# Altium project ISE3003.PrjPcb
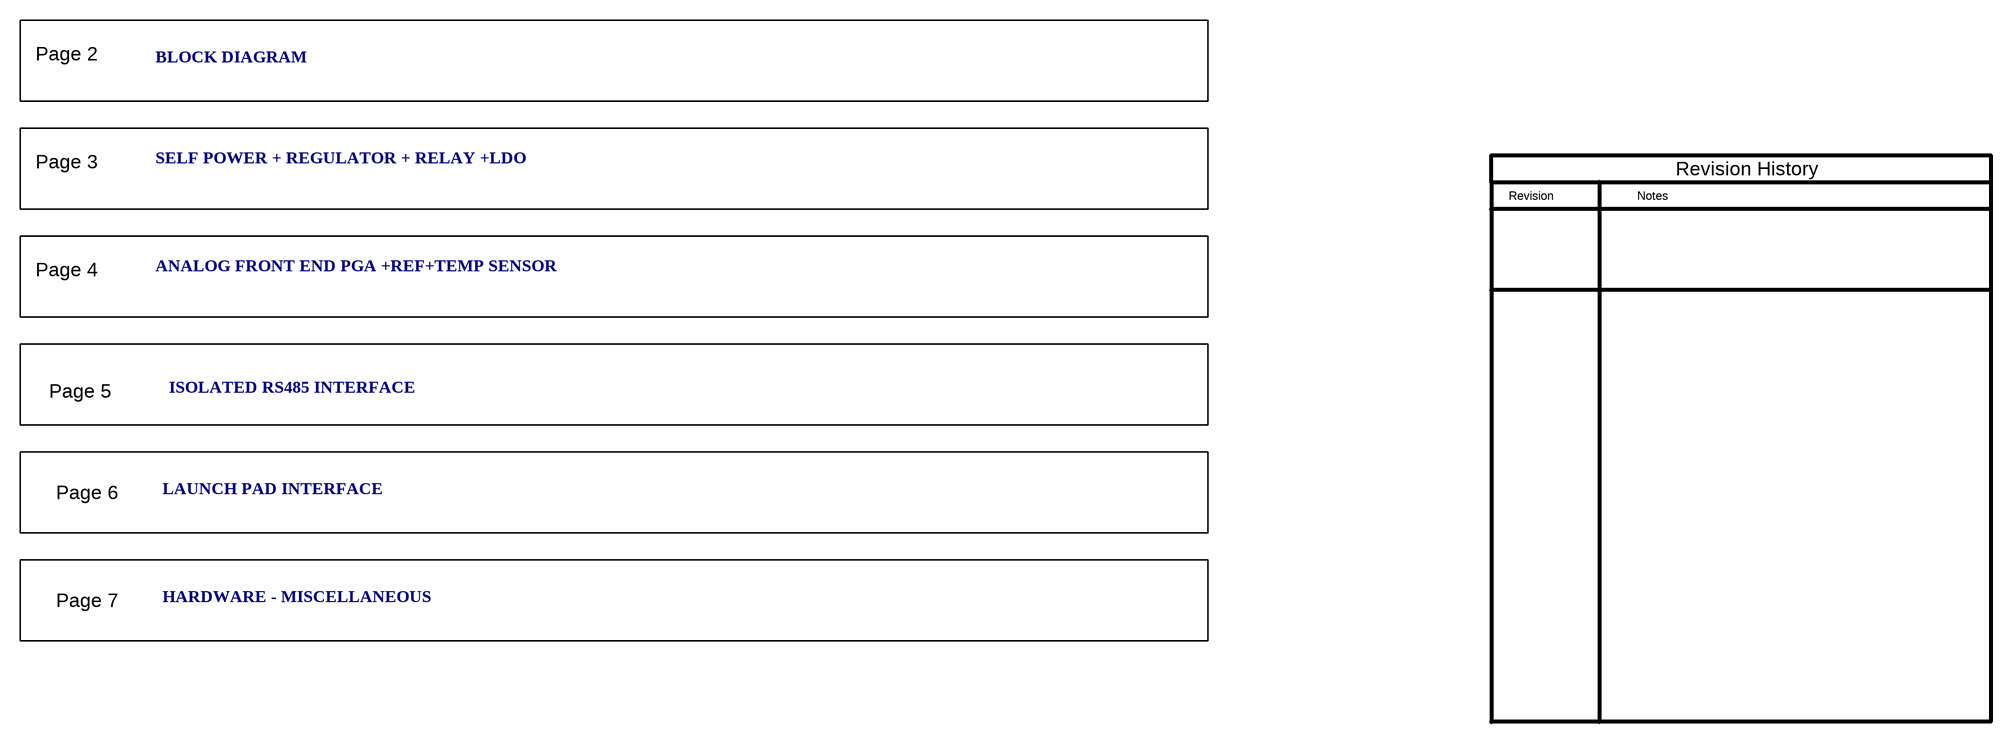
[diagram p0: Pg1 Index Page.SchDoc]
CopyrightYear: 2014; PCB_Layout: Who did the Layout?; PCB_Rev: E1; PRJ_Customer: Public Release; PRJ_Engineer: Enter name of project lead; PRJ_Number: TIDA-00191; PRJ_Title: AFE for Motor Electronic Overload Relays; SCH_Rev: E1; TechSupport: http://www.ti.com/support
7 sheets, 231 parts. Net scope: flat (ports and power ports of the same name join across sheets).
Board file: ISE3003.PcbDoc
Sheets:
  Pg1 Index Page.SchDoc
  Pg2 Block Diagram.SchDoc
  Pg3.SchDoc
  Pg4.SchDoc
  Pg5.SchDoc
  Pg6.SchDoc
  Pg7 Hardware.SchDoc

## Sheet Pg1 Index Page.SchDoc
size 431 x 279 mm; Date: Not shown in title block; ApprovedBy: Not shown in title block; CheckedBy: Not shown in title block; Author: Not shown in title block; CompanyName: Not shown in title block; Engineer: Not shown in title block; Organization: Not shown in title block; Address1: Not shown in title block; Address2: Not shown in title block; Address3: Not shown in title block; Address4: Not shown in title block; DocumentNumber: 1; Revision: Use project parameter SCH_Rev; SheetNumber: 1; SheetTotal: 7; PageSetup: Record=PageOptions|CenterHorizontal=True|CenterVertical=True|PrintScale=1.00|XCorrection=1.00|YCorrection=1.00|PrintKind=0|BorderSize=5000000|LeftOffset=0|BottomOffset=0|Orientation=2|PaperLength=1000|PaperWidth=1000|Scale=100|PaperSource=15|PrintQuality=600|MediaType=1|DitherType=10|PaperKind=Letter|PrintScaleMode=1

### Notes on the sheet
- Page 2
- BLOCK DIAGRAM
- Page 3
- SELF POWER + REGULATOR + RELAY +LDO
- Revision
- Notes
- Revision History
- Page 4
- ANALOG FRONT END PGA +REF+TEMP SENSOR
- Page 5
- ISOLATED RS485 INTERFACE
- Page 6
- LAUNCH PAD INTERFACE
- Page 7
- HARDWARE - MISCELLANEOUS

## Sheet Pg2 Block Diagram.SchDoc
size 431 x 279 mm; Date: Not shown in title block; ApprovedBy: Not shown in title block; CheckedBy: Not shown in title block; Author: Not shown in title block; CompanyName: Not shown in title block; Engineer: Not shown in title block; Organization: Not shown in title block; Address1: Not shown in title block; Address2: Not shown in title block; Address3: Not shown in title block; Address4: Not shown in title block; DocumentNumber: 2; Revision: Use project parameter SCH_Rev; SheetNumber: 2; SheetTotal: 7; PageSetup: Record=PageOptions|CenterHorizontal=True|CenterVertical=True|PrintScale=1.00|XCorrection=1.00|YCorrection=1.00|PrintKind=0|BorderSize=5000000|LeftOffset=0|BottomOffset=0|Orientation=2|PaperLength=1000|PaperWidth=1000|Scale=100|PaperSource=15|PrintQuality=600|MediaType=1|DitherType=10|PaperKind=Letter|PrintScaleMode=1
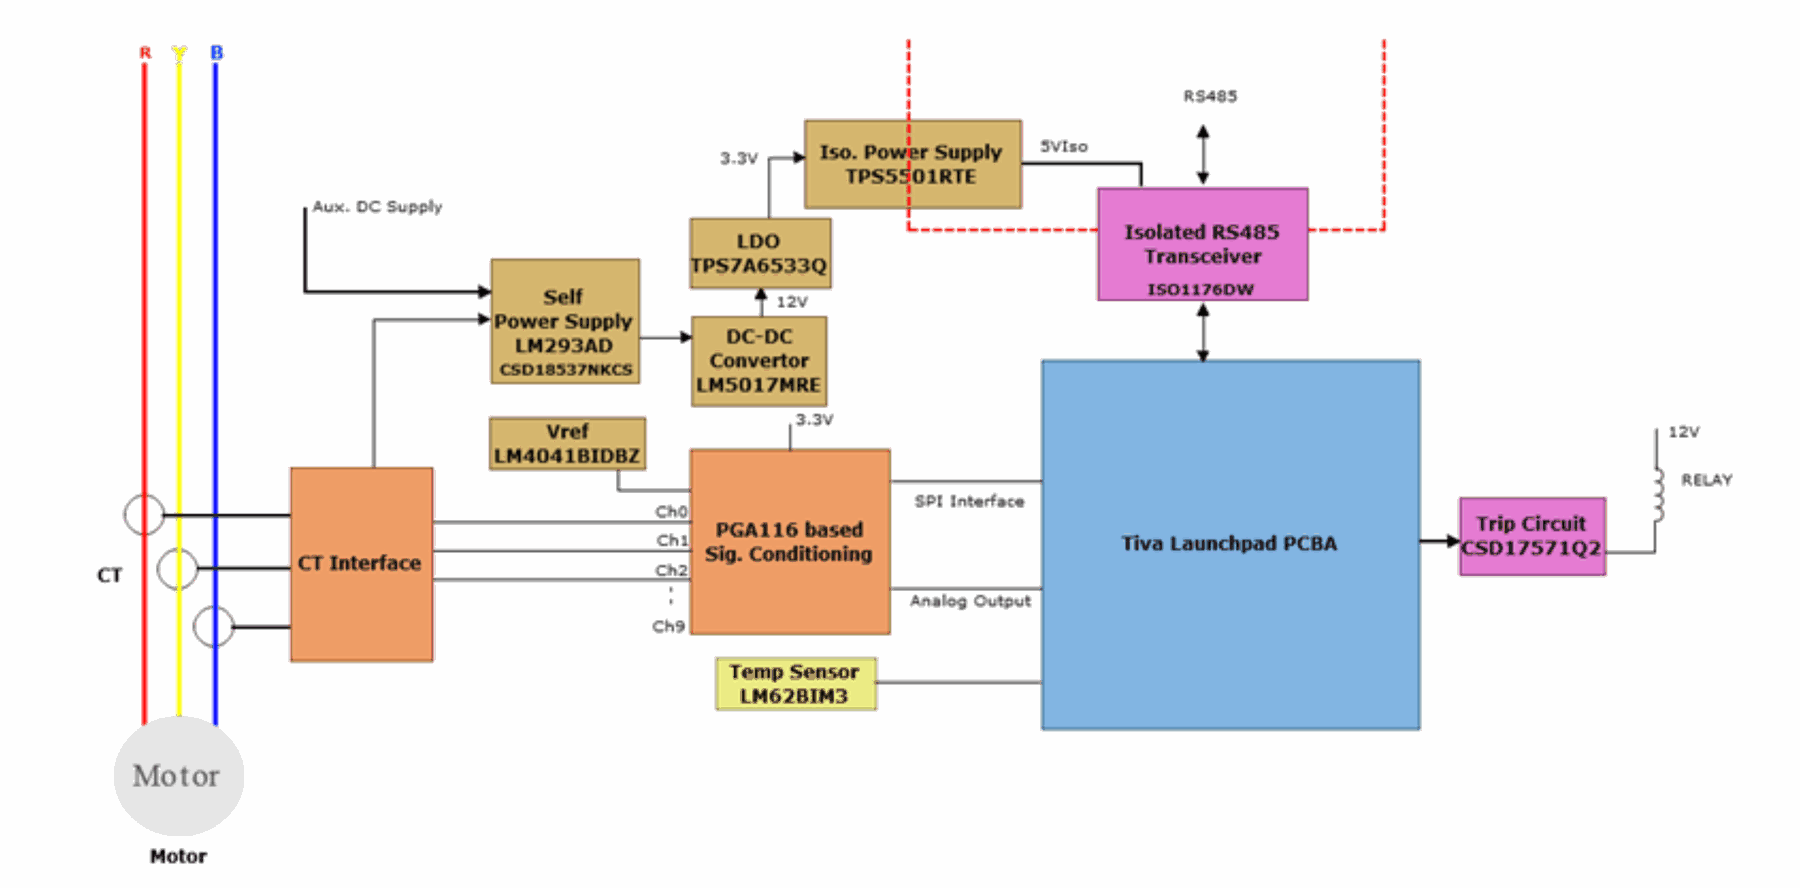
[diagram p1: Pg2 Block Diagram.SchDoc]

## Sheet Pg3.SchDoc
size 431 x 279 mm; Date: Not shown in title block; ApprovedBy: Not shown in title block; CheckedBy: Not shown in title block; Author: Not shown in title block; CompanyName: Not shown in title block; Engineer: Not shown in title block; Organization: Not shown in title block; Address1: Not shown in title block; Address2: Not shown in title block; Address3: Not shown in title block; Address4: Not shown in title block; DocumentNumber: 3; Revision: Use project parameter SCH_Rev; SheetNumber: 3; SheetTotal: 7; PageSetup: Record=PageOptions|CenterHorizontal=True|CenterVertical=True|PrintScale=1.00|XCorrection=1.00|YCorrection=1.00|PrintKind=0|BorderSize=5000000|LeftOffset=0|BottomOffset=0|Orientation=2|PaperLength=1000|PaperWidth=1000|Scale=100|PaperSource=15|PrintQuality=600|MediaType=1|DitherType=10|PaperKind=Letter|PrintScaleMode=1
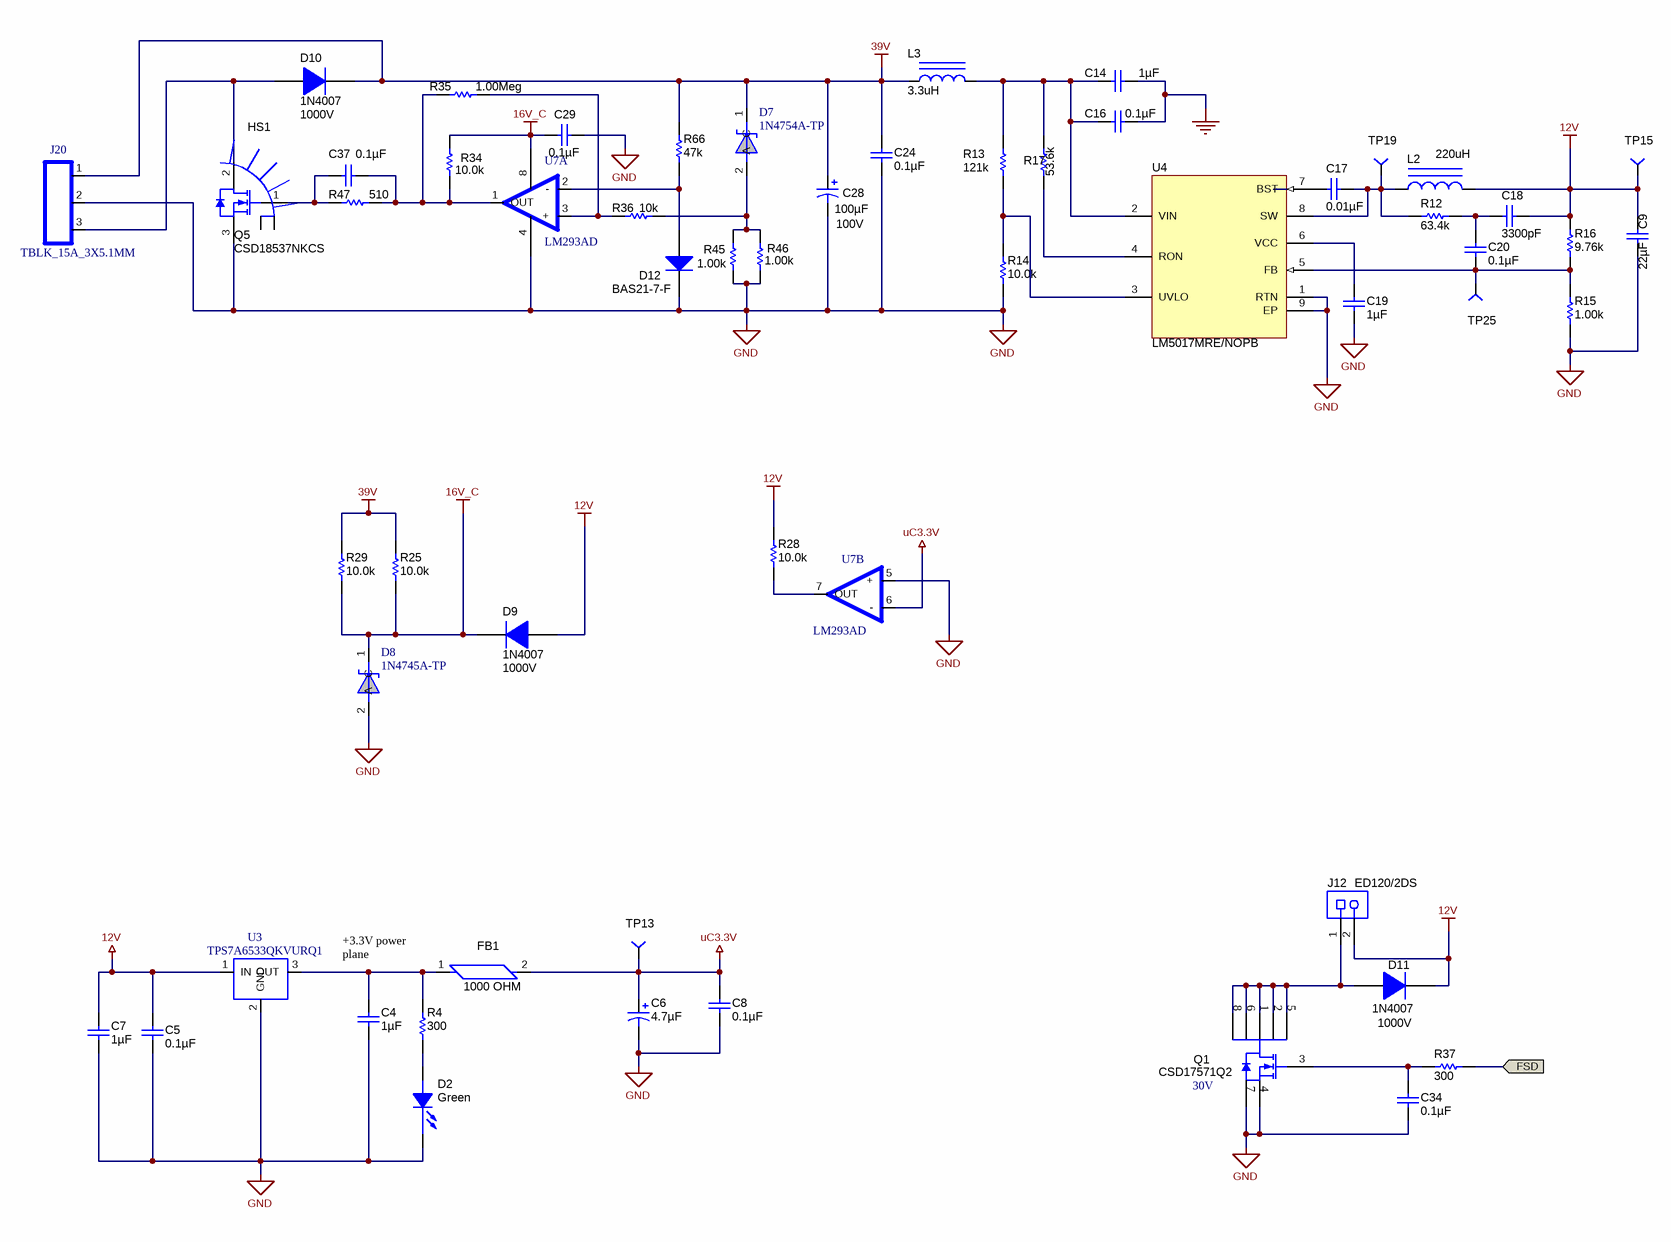
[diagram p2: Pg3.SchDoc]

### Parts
C4  ValueDisplayed: 1µF  [0603]  (hidden comment: C1608X7R1C105K)
C5  ValueDisplayed: 0.1µF  [0603]  (hidden comment: C0603C104K5RACTU)
C6  ValueDisplayed: 4.7µF  [6032-28]  (hidden comment: 293D475X9035C2TE3)
C7  ValueDisplayed: 1µF  [0603]  (hidden comment: C1608X7R1C105K)
C8  ValueDisplayed: 0.1µF  [0603]  (hidden comment: C0603C104K5RACTU)
C9  ValueDisplayed: 22µF  [1206]  (hidden comment: GRM31CR61C226KE15L)
C14  ValueDisplayed: 1µF  [1206]  (hidden comment: GRM31CR72A105KA01L)
C16  ValueDisplayed: 0.1µF  [0603]  (hidden comment: 06033C104JAT2A)
C17  ValueDisplayed: 0.01µF  [0603]  (hidden comment: C1608C0G1E103J)
C18  ValueDisplayed: 3300pF  [0603]  (hidden comment: C0603C332K5RACTU)
C19  ValueDisplayed: 1µF  [0603]  (hidden comment: C1608X5R1E105K080AC)
C20  ValueDisplayed: 0.1µF  [0603]  (hidden comment: 06033C104JAT2A)
C24  ValueDisplayed: 0.1µF  [0805_HV]  (hidden comment: C0805C104K1RACTU)
C28  ValueDisplayed: 100µF  Value2: 100V  [YXJ_1000x2000]  (hidden comment: 100YXJ100M10X20)
C29  ValueDisplayed: 0.1µF  [0603]  (hidden comment: C0603C104K5RACTU)
C34  ValueDisplayed: 0.1µF  [0603]  (hidden comment: 06033C104JAT2A)
C37  ValueDisplayed: 0.1µF  [0603]  (hidden comment: 06033C104JAT2A)
D2  value Green  [LED0603AA]  (hidden comment: LED_LG L29K-G2J1-24-Z)
D7  1N4754A-TP  [DO-41]
D8  1N4745A-TP  [DO-41]
D9  1N4007  value 1000V  [DO-41]
D10  1N4007  value 1000V  [DO-41]
D11  1N4007  value 1000V  [DO-41]
D12  BAS21-7-F  [SOT-23]
FB1  1000 OHM  [0603]
HS1  HEATSINK_513102B02500G  [HEATSINK_513201]  (value not drawn)
J12  ED120/2DS  [CONN_ED120-2DS]
J20  TBLK_15A_3X5.1MM  [TB_3X5.1MM]
L2  value 220uH  [SRR7045]  (hidden comment: SRR7032-221M)
L3  value 3.3uH  [1210]  (hidden comment: B82422H1332K)
Q1  CSD17571Q2  value 30V  [SON_CSD17571Q2]
Q5  CSD18537NKCS  [TO-220AB]
R4  value 300  [0603]  (hidden comment: CRCW0603300RJNEA)
R12  value 63.4k  [0603]  (hidden comment: CRCW060363K4FKEA)
R13  value 121k  [0805_HV]  (hidden comment: RT0805BRD07121KL)
R14  value 10.0k  [0603]  (hidden comment: CRCW060310K0FKEA)
R15  value 1.00k  [0603]  (hidden comment: RC0603FR-071KL)
R16  value 9.76k  [0603]  (hidden comment: CRCW06039K76FKEA)
R17  value 53.6k  [0805_HV]  (hidden comment: RG2012P-5362-B-T5)
R25  value 10.0k  [1206]  (hidden comment: CRCW120610K0FKEA)
R28  value 10.0k  [0603]  (hidden comment: CRCW060310K0FKEA)
R29  value 10.0k  [1206]  (hidden comment: CRCW120610K0FKEA)
R34  value 10.0k  [1206]  (hidden comment: CRCW120610K0FKEA)
R35  value 1.00Meg  [0603]  (hidden comment: CRCW06031M00FKEA)
R36  value 10k  [0603]  (hidden comment: RNCF0603TKY10K0)
R37  value 300  [0603]  (hidden comment: CRCW0603300RJNEA)
R45  value 1.00k  [1206]  (hidden comment: CRCW12061K00FKEA)
R46  value 1.00k  [1206]  (hidden comment: CRCW12061K00FKEA)
R47  value 510  [0603]  (hidden comment: RG1608P-511-B-T5)
R66  value 47k  [0805_HV]  (hidden comment: ERJ-6GEYJ473V)
TP13  TP-040_RND  [TP-040_RND]  (value not drawn)
TP15  TP-040_RND  [TP-040_RND]  (value not drawn)
TP19  TP-040_RND  [TP-040_RND]  (value not drawn)
TP25  TP-040_RND  [TP-040_RND]  (value not drawn)
U3  TPS7A6533QKVURQ1  [KVU_1]
U4  LM5017MRE/NOPB  [DDA0008B_N]
U7  LM293AD  [SO8]  (parts A,B of 2)

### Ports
FSD (in)

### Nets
12V: C5.1 C7.1 C9.1 C18.1 D9.2(A) D11.1(K) J12.2 L2.2 R16.2 R28.2 TP15.1 U3.1(IN)
16V_C: C29.1 D8.1(C) D9.1(K) R25.1 R29.1 R34.1 U7.8(VCC)
39V: C24.1 C28.1(+) D7.1(C) D10.1(K) J20.1 L3.1 R25.2 R29.2 R66.2
GND: C4.2 C5.2 C6.2(-) C7.2 C8.2 C9.2 C14.1 C16.2 C19.2 C24.2 C28.2(-) C29.2 C34.2 D2.1(C) D8.2(A) D12.3(K) J20.2 Q1.4(S) Q1.7(S) Q5.3(S) R14.1 R15.1 R45.1 R46.1 U3.2(GND) U4.1(RTN) U4.9(EP) U7.4(GND) U7.5(+)
uC3.3V: C6.1(+) C8.1 FB1.2 TP13.1 U7.6(-)
FSD: R37.1 ; port FSD
NetC4_1: C4.1 FB1.1 R4.2 U3.3(OUT)
NetC14_2: C14.2 C16.1 L3.2 R13.2 R17.2 U4.2(VIN)
NetC17_1: C17.1 U4.7(BST)
NetC17_2: C17.2 L2.1 R12.1 TP19.1 U4.8(SW)
NetC18_2: C18.2 C20.2 R12.2
NetC19_1: C19.1 U4.6(VCC)
NetC20_1: C20.1 R15.2 R16.1 TP25.1 U4.5(FB)
NetC34_1: C34.1 Q1.3(G) R37.2
NetC37_1: C37.1 R34.2 R35.2 R47.1 U7.1(OUT)
NetC37_2: C37.2 Q5.1(G) R47.2
NetD2_2: D2.2(A) R4.1
NetD7_2: D7.2(A) R36.2 R45.2 R46.2
NetD10_2: D10.2(A) J20.3 Q5.2(D)
NetD11_2: D11.2(A) J12.1 Q1.1(D) Q1.2(D) Q1.5(D) Q1.6(D) Q1.8(D)
NetD12_1: D12.1(A) R66.1 U7.2(-)
NetR13_1: R13.1 R14.2 U4.3(UVLO)
NetR17_1: R17.1 U4.4(RON)
NetR28_1: R28.1 U7.7(OUT)
NetR35_1: R35.1 R36.1 U7.3(+)

Not connected (* = marked no-connect by the designer): HS1 1 2

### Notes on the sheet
- (near FB1) +3.3V power
  plane

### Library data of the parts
C4 C7 = C1608X7R1C105K: CAP, CERM, 1uF, 16V, +/-10%, X7R, 0603; Manufacturer: TDK; Polarized: N; CompType: Capacitor; U/M: EA; Cap_F: 0.000001; Tolerance_%: 10; ESR_Ohm: 0.0057; Value1: 0.0057 ohm; VDC_V: 16; TaMin_C: -55; TaMax_C: 125
C5 C8 C29 = C0603C104K5RACTU: CAP, CERM, 0.1uF, 50V, +/-10%, X7R, 0603; Manufacturer: Kemet; Polarized: N; CompType: Capacitor; U/M: EA; Cap_F: 0.0000001; Tolerance_%: 10; Value1: Unknown; VDC_V: 50; TaMin_C: -55; TaMax_C: 125
C6 = 293D475X9035C2TE3: CAP, TA, 4.7uF, 35V, +/-10%, 1.9 ohm, SMD; Manufacturer: Vishay-Sprague; Polarized: Y; CompType: Capacitor; U/M: EA; Cap_F: 0.0000047; Tolerance_%: 10; Value1: 1.9 ohm; VDC_V: 35; ESR_Ohm: 1.9; IRMS_A: 0.24; TaMin_C: -55; TaMax_C: 125; Cap_Case: C
C9 = GRM31CR61C226KE15L: CAP, CERM, 22uF, 16V, +/-10%, X5R, 1206; Manufacturer: MuRata; Polarized: N; CompType: Capacitor; U/M: EA; Cap_F: 0.000022; Tolerance_%: 10; Value1: Unknown; VDC_V: 16; TaMin_C: -55; TaMax_C: 85
C14 = GRM31CR72A105KA01L: CAP, CERM, 1uF, 100V, +/-10%, X7R, 1206; Manufacturer: MuRata; Polarized: N; CompType: Capacitor; U/M: EA; Cap_F: 0.000001; Tolerance_%: 10; Value1: Unknown; VDC_V: 100; TaMin_C: -55; TaMax_C: 125; Cap_Case: 2220
C16 C20 C34 C37 = 06033C104JAT2A: CAP, CERM, 0.1uF, 25V, +/-5%, X7R, 0603; Manufacturer: AVX; Polarized: N; CompType: Capacitor; U/M: EA; Cap_F: 0.0000001; Tolerance_%: 5; ESR_Ohm: 0.05; Value1: 0.05 ohm; VDC_V: 25; TaMin_C: -55; TaMax_C: 125
C17 = C1608C0G1E103J: CAP, CERM, 0.01uF, 25V, +/-5%, C0G/NP0, 0603; Manufacturer: TDK; Polarized: N; CompType: Capacitor; U/M: EA; Cap_F: 0.00000001; Tolerance_%: 5; Value1: Unknown; VDC_V: 25; TaMin_C: -55; TaMax_C: 125
C18 = C0603C332K5RACTU: CAP, CERM, 3300pF, 50V, +/-10%, X7R, 0603; Manufacturer: Kemet; Polarized: N; CompType: Capacitor; U/M: EA; Cap_F: 0.0000000033; Tolerance_%: 10; Value1: Unknown; VDC_V: 50; TaMin_C: -55; TaMax_C: 125
C19 = C1608X5R1E105K080AC: CAP, CERM, 1uF, 25V, +/-10%, X5R, 0603; Manufacturer: TDK; Polarized: N; CompType: Capacitor; U/M: EA; Cap_F: 0.000001; Tolerance_%: 10; Value1: Unknown; VDC_V: 25; TaMin_C: -55; TaMax_C: 85
C24 = C0805C104K1RACTU: CAP, CERM, 0.1uF, 100V, +/-10%, X7R, 0805; Manufacturer: Kemet; Polarized: N; CompType: Capacitor; U/M: EA; Cap_F: 0.0000001; Tolerance_%: 10; ESR_Ohm: 0.064; Value1: 0.064 ohm; VDC_V: 100; IRMS_A: 1.64; TaMin_C: -55; TaMax_C: 125; Cap_Case: 0805
C28 = 100YXJ100M10X20: CAP, AL, 100uF, 100V, +/-20%, 0.12 ohm, TH; Manufacturer: Rubycon; Polarized: Y; CompType: Capacitor; U/M: EA; Cap_F: 0.0001; Tolerance_%: 20; VDC_V: 100; ESR_Ohm: 0.12; IRMS_A: 1.04; TaMin_C: -40; TaMax_C: 105; Cap_Case: 10x20
D2 = LED_LG L29K-G2J1-24-Z: LED SmartLED Green 570NM; Manufacturer: OSRAM; SymbolCreator: x0120606
D7 = 1N4754A-TP: Diode, Zener, 39V, 1W, DO41; Manufacturer: Micro Commercial Co; Area: 54000
D8 = 1N4745A-TP: Diode, Zener, 16V, 1W, DO41; Manufacturer: Micro Commercial Co; Area: 54000
D9-D11 = 1N4007: Diode, P-N, 1000V, 1A, TH; Manufacturer: Fairchild Semiconductor; U/M: EA; Vf_V: 1.1; Value2: 1.1V; Io_A: 1; Vr_V: 1000; TJmax_C: 175; RJC_CperW: 50
D12 = BAS21-7-F: Diode, Switching, 200V, 0.2A, SOT-23; Manufacturer: Diodes Inc.; U/M: EA; Vf_V: 1.25; Value2: 1.25V; Io_A: 0.2; Vr_V: 200; TJmax_C: 150; RJC_CperW: 500
FB1 = MMZ1608B102C: FERRITE CHIP 1000 OHM 300MA 0603; Manufacturer: TDK Corporation; CompType: Ferrite Bead
HS1 = HEATSINK_513201: HEATSINK TO-220 W/PINS 1.5"TALL; Manufacturer: Aavid Thermalloy; area: 739800
J12 = ED120/2DS: TERMINAL BLOCK 5.08MM VERT 2POS, TH; Manufacturer: On-Shore Technology; SymbolCreator: a0412235; U/M: EA
J20 = TBLK_15A_3X5.1MM: Terminal Block, 3-pin, 15-A, 5.1mm; Manufacturer: OST; PartNumber: ED120/3DS; area: 212400; Value: ED120/3DS
L2 = IND_SRR7032-221M: Inductor, 220uH .30A SMD; Manufacturer: Bourns; Material: Ferrite
L3 = IND_B82422H1332K: Inductor, Chip, 3.3uH 770MA 1210 10%; Manufacturer: EPCOS Inc; Area: 28000
Q1 = CSD17571Q2: MOSFET, N-CH, 30V, 22A, SON 2X2 MM; Manufacturer: TEXAS INSTRUMENTS; CompType: POWER MOSFET
Q5 = CSD18537NKCS: MOSFET, N-CH, 60V, 50A, TO-220AB; Manufacturer: Texas Instruments; Alternate Manufacturer: None; ChType: N
R4 R37 = CRCW0603300RJNEA: RES, 300 ohm, 5%, 0.1W, 0603; Manufacturer: Vishay-Dale; CompType: Resistor; Value_Code: 300R; Tolerance_%: 5; Power_W: 0.1; VDC_V: 75; TempCo: 200 ppm/C; EIA_Code: E24; U/M: EA
R12 = CRCW060363K4FKEA: RES, 63.4k ohm, 1%, 0.1W, 0603; Manufacturer: Vishay-Dale; CompType: Resistor; Res_ohm: 63400; Value_Code: 63k4; Tolerance_%: 1; Power_W: 0.1; VDC_V: 75; TempCo: 100 ppm/C; EIA_Code: E96; U/M: EA
R13 = RT0805BRD07121KL: RES, 121k ohm, 0.1%, 0.125W, 0805; Manufacturer: Yageo America; CompType: Resistor; Res_ohm: 121000; Tolerance_%: 0.1; Power_W: 0.125; VDC_V: 150; TempCo: 25 ppm/C; EIA_Code: E192; U/M: EA
R14 R28 = CRCW060310K0FKEA: RES, 10.0k ohm, 1%, 0.1W, 0603; Manufacturer: Vishay-Dale; CompType: Resistor; Res_ohm: 10000; Value_Code: 10k0; Tolerance_%: 1; Power_W: 0.1; VDC_V: 75; TempCo: 100 ppm/C; EIA_Code: E96; U/M: EA
R15 = RC0603FR-071KL: RES, 1.00k ohm, 1%, 0.1W, 0603; Manufacturer: Yageo America; CompType: Resistor; Res_ohm: 1000; Value_Code: 1k00; Tolerance_%: 1; Power_W: 0.1; VDC_V: 150; TempCo: 200 ppm/C; EIA_Code: E96; U/M: EA
R16 = CRCW06039K76FKEA: RES, 9.76k ohm, 1%, 0.1W, 0603; Manufacturer: Vishay-Dale; CompType: Resistor; Res_ohm: 9760; Value_Code: 9k76; Tolerance_%: 1; Power_W: 0.1; VDC_V: 75; TempCo: 100 ppm/C; EIA_Code: E96; U/M: EA
R17 = RG2012P-5362-B-T5: RES, 53.6k ohm, 0.1%, 0.125W, 0805; Manufacturer: Susumu Co Ltd; CompType: Resistor; Res_ohm: 53600; Value_Code: 53k6; Tolerance_%: 0.1; Power_W: 0.125; VDC_V: 100; TempCo: 25 ppm/C; EIA_Code: E192; U/M: EA
R25 R29 R34 = CRCW120610K0FKEA: RES, 10.0k ohm, 1%, 0.25W, 1206; Manufacturer: Vishay-Dale; CompType: Resistor; Res_ohm: 10000; Value_Code: 10k0; Tolerance_%: 1; Power_W: 0.25; VDC_V: 200; TempCo: 100 ppm/C; EIA_Code: E96; U/M: EA
R35 = CRCW06031M00FKEA: RES, 1.00Meg ohm, 1%, 0.1W, 0603; Manufacturer: Vishay-Dale; CompType: Resistor; Res_ohm: 1000000; Value_Code: 1M00; Tolerance_%: 1; Power_W: 0.1; VDC_V: 75; TempCo: 100 ppm/C; EIA_Code: E96; U/M: EA
R36 = RNCF0603TKY10K0: RES, 10k ohm, 0.01%, 0.063W, 0603; Manufacturer: Stackpole Electronics Inc; CompType: Resistor; Res_ohm: 10000; Value_Code: 10k0; Tolerance_%: 0.01; Power_W: 0.063; VDC_V: 50; TempCo: 5 ppm/C; U/M: EA
R45 R46 = CRCW12061K00FKEA: RES, 1.00k ohm, 1%, 0.25W, 1206; Manufacturer: Vishay-Dale; CompType: Resistor; Res_ohm: 1000; Value_Code: 1k00; Tolerance_%: 1; Power_W: 0.25; VDC_V: 200; TempCo: 100 ppm/C; EIA_Code: E96; U/M: EA
R47 = RG1608P-511-B-T5: RES, 510 ohm, 0.1%, 0.1W, 0603; Manufacturer: Susumu Co Ltd; CompType: Resistor; Value_Code: 510R; Tolerance_%: 0.1; VDC_V: 75; TempCo: 25 ppm/C; U/M: EA
R66 = ERJ-6GEYJ473V: RES, 47k ohm, 5%, 0.125W, 0805; Manufacturer: Panasonic; CompType: Resistor; Res_ohm: 47000; Value_Code: 47k0; Tolerance_%: 5; Power_W: 0.125; VDC_V: 150; TempCo: 200 ppm/C; EIA_Code: E24; U/M: EA
TP13 TP15 TP19 TP25 = TP-040_RND: Test Point, O.040 Hole; Manufacturer: STD; Value: STD
U3 = TPS7A6533QKVURQ1: IC, 300-mA 40-V LOW-DROPOUT REGULATOR WITH 25-uA QUIESCENT CURRENT; Manufacturer: TI; Alternate Manufacturer: None; Area: 136210
U4 = LM5017MRE/NOPB: 100V, 600mA Constant On-Time Synchronous Buck Regulator, DDA0008B; Alternate Manufacturer: None; Manufacturer: Texas Instruments; SymbolCreator: a0412235; CompType: IC; U/M: EA
U7 = LM293AD: IC, Dual Differential Comparators, 2-36 Vin; Manufacturer: TI; Alternate Manufacturer: None; Area: 75900

## Sheet Pg4.SchDoc
size 431 x 279 mm; Date: Not shown in title block; ApprovedBy: Not shown in title block; CheckedBy: Not shown in title block; Author: Not shown in title block; CompanyName: Not shown in title block; Engineer: Not shown in title block; Organization: Not shown in title block; Address1: Not shown in title block; Address2: Not shown in title block; Address3: Not shown in title block; Address4: Not shown in title block; DocumentNumber: 4; Revision: Use project parameter SCH_Rev; SheetNumber: 4; SheetTotal: 7; PageSetup: Record=PageOptions|CenterHorizontal=True|CenterVertical=True|PrintScale=0.59|XCorrection=1.00|YCorrection=1.00|PrintKind=0|BorderSize=5000000|LeftOffset=0|BottomOffset=0|Orientation=2|PaperLength=1000|PaperWidth=1000|Scale=100|PaperSource=15|PrintQuality=600|MediaType=1|DitherType=10|PaperKind=Letter|PrintScaleMode=1
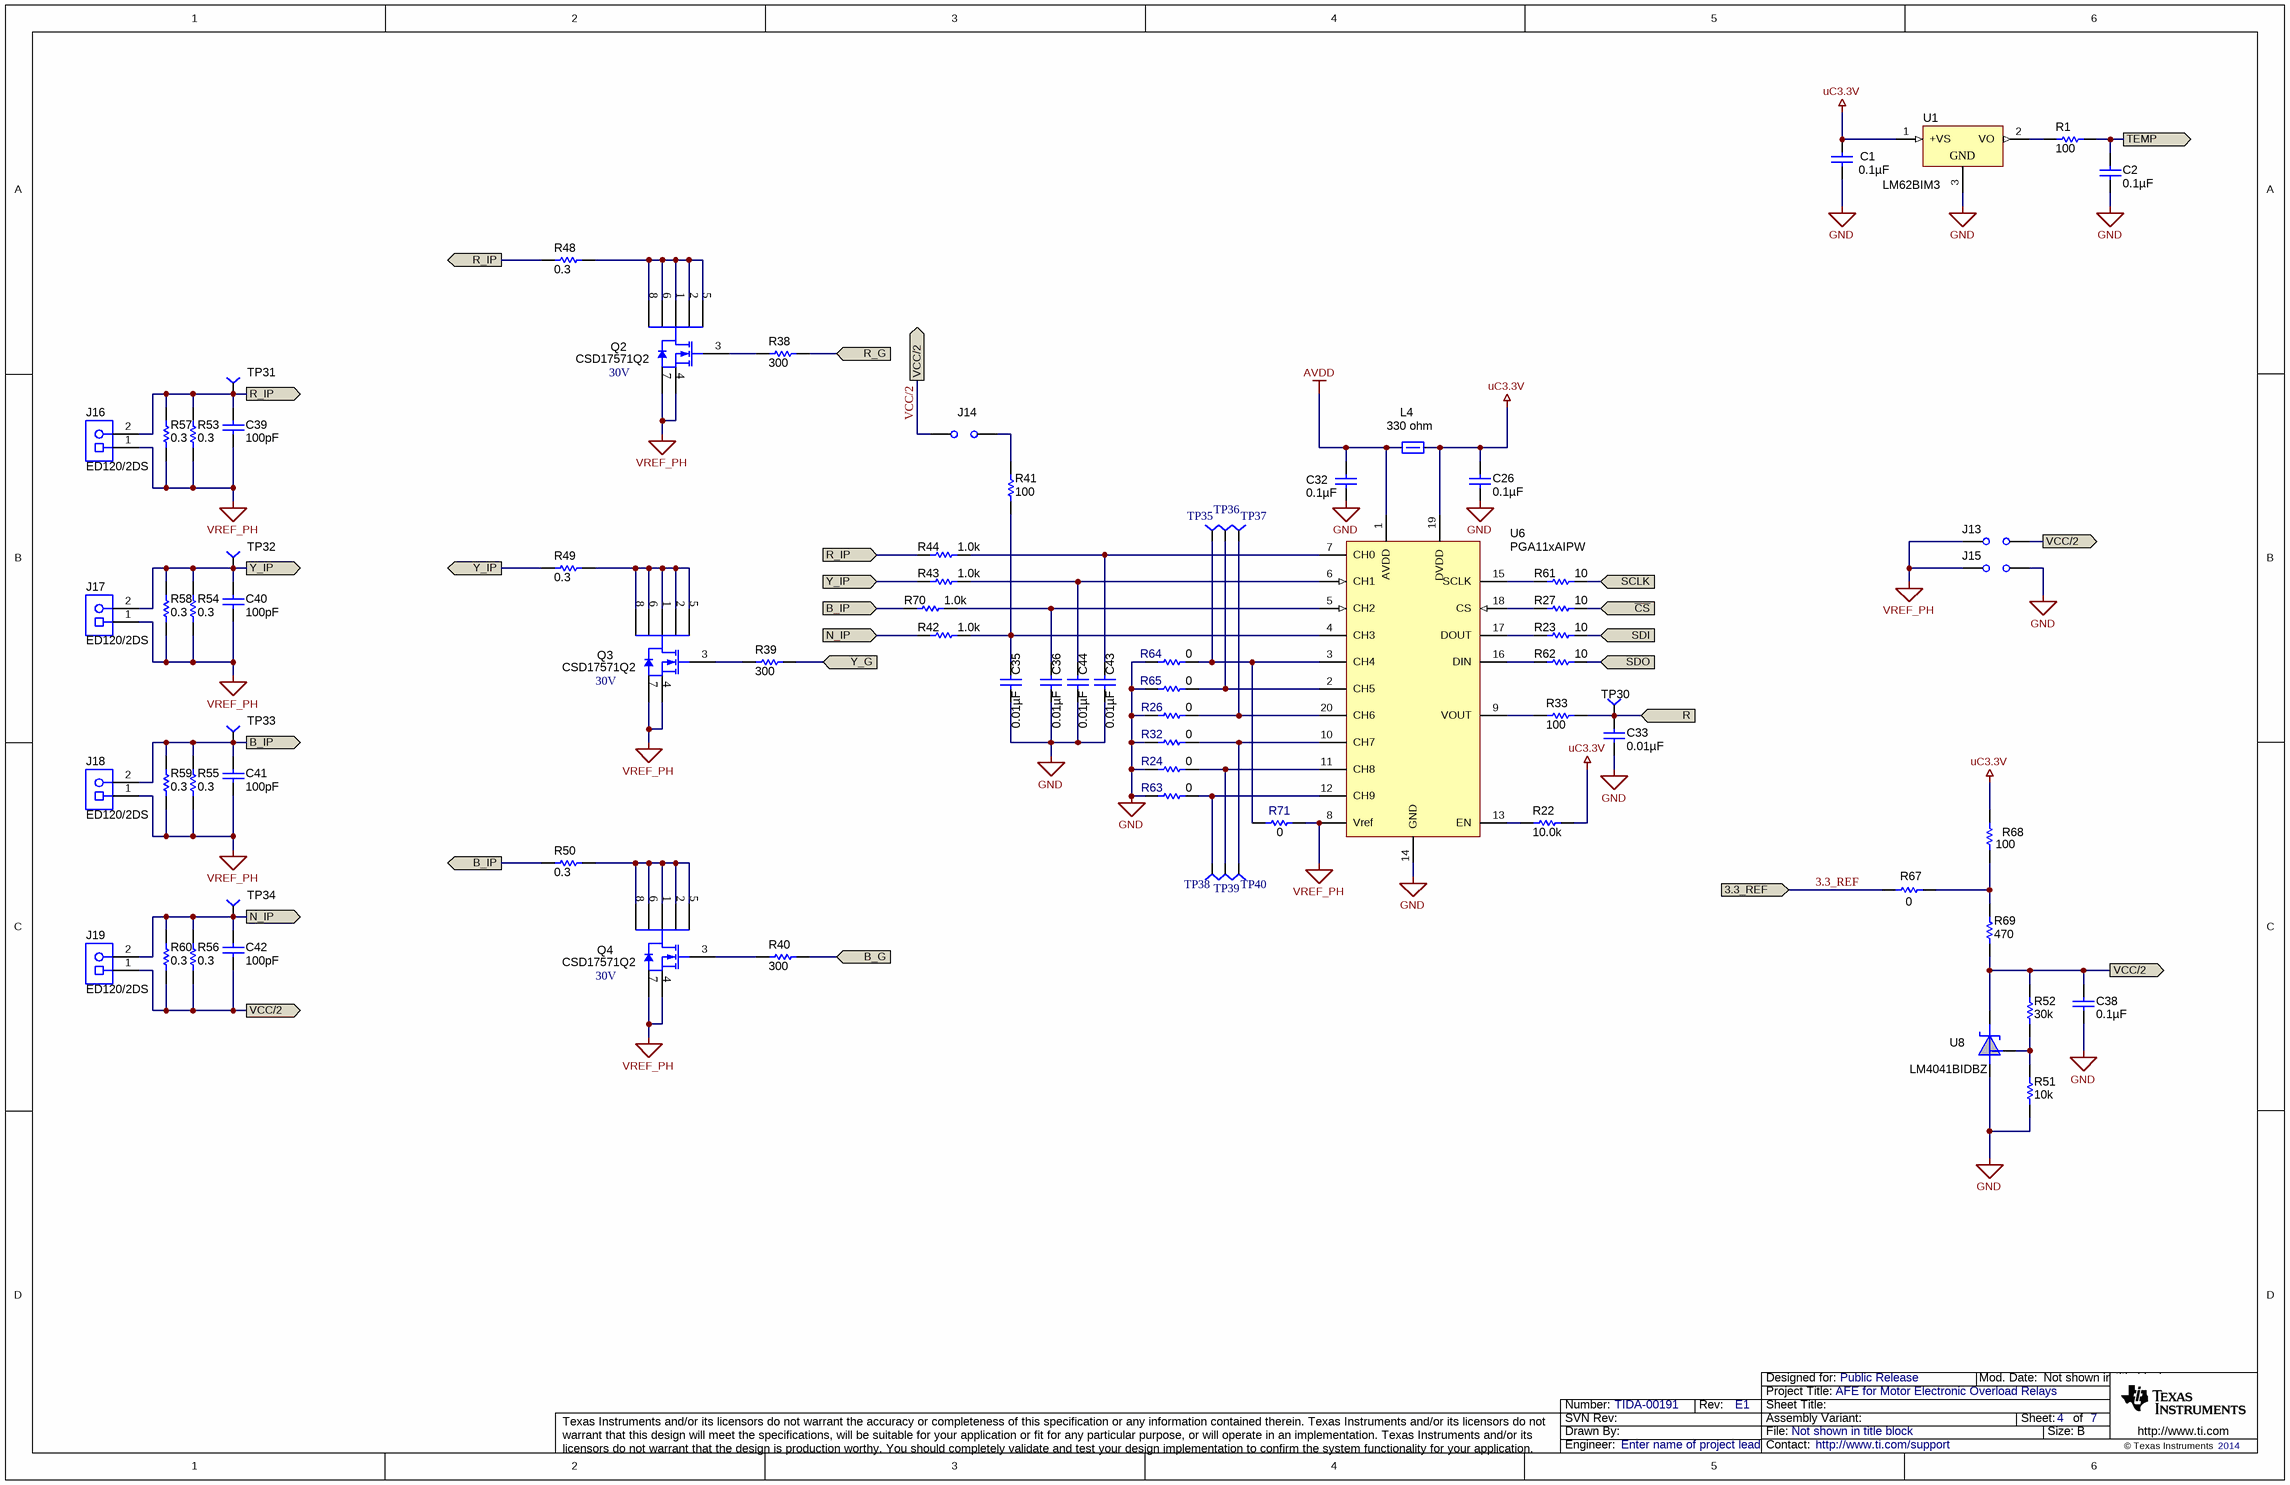
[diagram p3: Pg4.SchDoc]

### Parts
C1  ValueDisplayed: 0.1µF  [0603]  (hidden comment: 06033C104JAT2A)
C2  ValueDisplayed: 0.1µF  [0603]  (hidden comment: 06033C104JAT2A)
C26  ValueDisplayed: 0.1µF  [0603]  (hidden comment: 06033C104JAT2A)
C32  ValueDisplayed: 0.1µF  [0603]  (hidden comment: 06033C104JAT2A)
C33  ValueDisplayed: 0.01µF  [0603]  (hidden comment: C1608C0G1E103J)
C35  ValueDisplayed: 0.01µF  [0603]  (hidden comment: C1608C0G1E103J)
C36  ValueDisplayed: 0.01µF  [0603]  (hidden comment: C1608C0G1E103J)
C38  ValueDisplayed: 0.1µF  [0603]  (hidden comment: 06033C104JAT2A)
C39  ValueDisplayed: 100pF  [0603]  (hidden comment: 06033C101KAT2A)
C40  ValueDisplayed: 100pF  [0603]  (hidden comment: 06033C101KAT2A)
C41  ValueDisplayed: 100pF  [0603]  (hidden comment: 06033C101KAT2A)
C42  ValueDisplayed: 100pF  [0603]  (hidden comment: 06033C101KAT2A)
C43  ValueDisplayed: 0.01µF  [0603]  (hidden comment: C1608C0G1E103J)
C44  ValueDisplayed: 0.01µF  [0603]  (hidden comment: C1608C0G1E103J)
J13  JUMPER_2X100MIL  [HDR100_1X2]  (value not drawn)
J14  JUMPER_2X100MIL  [HDR100_1X2]  (value not drawn)
J15  JUMPER_2X100MIL  [HDR100_1X2]  (value not drawn)
J16  ED120/2DS  [CONN_ED120-2DS]
J17  ED120/2DS  [CONN_ED120-2DS]
J18  ED120/2DS  [CONN_ED120-2DS]
J19  ED120/2DS  [CONN_ED120-2DS]
L4  value 330 ohm  [0603]  (hidden comment: BLM18SG331TN1D)
Q2  CSD17571Q2  value 30V  [SON_CSD17571Q2]
Q3  CSD17571Q2  value 30V  [SON_CSD17571Q2]
Q4  CSD17571Q2  value 30V  [SON_CSD17571Q2]
R1  value 100  [0603]  (hidden comment: CRCW0603100RFKEA)
R22  value 10.0k  [0603]  (hidden comment: CRCW060310K0FKEA)
R23  value 10  [0603]  (hidden comment: CRCW060310R0JNEA)
R24  value 0  [0603]  (hidden comment: CRCW06030000Z0EA)
R26  value 0  [0603]  (hidden comment: CRCW06030000Z0EA)
R27  value 10  [0603]  (hidden comment: CRCW060310R0JNEA)
R32  value 0  [0603]  (hidden comment: CRCW06030000Z0EA)
R33  value 100  [0603]  (hidden comment: CRCW0603100RFKEA)
R38  value 300  [0603]  (hidden comment: CRCW0603300RJNEA)
R39  value 300  [0603]  (hidden comment: CRCW0603300RJNEA)
R40  value 300  [0603]  (hidden comment: CRCW0603300RJNEA)
R41  value 100  [0603]  (hidden comment: CRCW0603100RFKEA)
R42  value 1.0k  [0603]  (hidden comment: CRCW06031K00JNEA)
R43  value 1.0k  [0603]  (hidden comment: CRCW06031K00JNEA)
R44  value 1.0k  [0603]  (hidden comment: CRCW06031K00JNEA)
R48  value 0.3  [1206]  (hidden comment: CSR1206FKR300)
R49  value 0.3  [1206]  (hidden comment: CSR1206FKR300)
R50  value 0.3  [1206]  (hidden comment: CSR1206FKR300)
R51  value 10k  [0603]  (hidden comment: RNCF0603TKY10K0)
R52  value 30k  [0603]  (hidden comment: CRCW060330K0JNEA)
R53  value 0.3  [1206]  (hidden comment: CSR1206FKR300)
R54  value 0.3  [1206]  (hidden comment: CSR1206FKR300)
R55  value 0.3  [1206]  (hidden comment: CSR1206FKR300)
R56  value 0.3  [1206]  (hidden comment: CSR1206FKR300)
R57  value 0.3  [1206]  (hidden comment: CSR1206FKR300)
R58  value 0.3  [1206]  (hidden comment: CSR1206FKR300)
R59  value 0.3  [1206]  (hidden comment: CSR1206FKR300)
R60  value 0.3  [1206]  (hidden comment: CSR1206FKR300)
R61  value 10  [0603]  (hidden comment: CRCW060310R0JNEA)
R62  value 10  [0603]  (hidden comment: CRCW060310R0JNEA)
R63  value 0  [0603]  (hidden comment: CRCW06030000Z0EA)
R64  value 0  [0603]  (hidden comment: CRCW06030000Z0EA)
R65  value 0  [0603]  (hidden comment: CRCW06030000Z0EA)
R67  value 0  [0603]  (hidden comment: CRCW06030000Z0EA)
R68  value 100  [0603]  (hidden comment: CRCW0603100RFKEA)
R69  value 470  [0603]  (hidden comment: CRCW0603470RJNEA)
R70  value 1.0k  [0603]  (hidden comment: CRCW06031K00JNEA)
R71  value 0  [0603]  (hidden comment: CRCW06030000Z0EA)
TP30  TP-040_RND  [TP-040_RND]  (value not drawn)
TP31  TP-040_RND  [TP-040_RND]  (value not drawn)
TP32  TP-040_RND  [TP-040_RND]  (value not drawn)
TP33  TP-040_RND  [TP-040_RND]  (value not drawn)
TP34  TP-040_RND  [TP-040_RND]  (value not drawn)
TP35  TP-040_RND  [TP-040_RND]  (value not drawn)
TP36  TP-040_RND  [TP-040_RND]  (value not drawn)
TP37  TP-040_RND  [TP-040_RND]  (value not drawn)
TP38  TP-040_RND  [TP-040_RND]  (value not drawn)
TP39  TP-040_RND  [TP-040_RND]  (value not drawn)
TP40  TP-040_RND  [TP-040_RND]  (value not drawn)
U1  LM62BIM3  [MF03A_N]
U6  PGA11xAIPW  [PW0020A_L]
U8  LM4041BIDBZ  [SOT-23]

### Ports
3.3_REF (in), B_G (in), B_IP (in), B_IP (out), N_IP (in), N_IP (out), R (in), R_G (in), R_IP (in), R_IP (out), SCLK (in), SDI (in), SDO (in), TEMP (out), VCC/2 (out), Y_G (in), Y_IP (in), Y_IP (out), ~{CS} (in)

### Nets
AVDD: C32.2 L4.1 U6.1(AVDD)
GND: C1.2 C2.1 C26.1 C32.1 C33.2 C35.2 C36.2 C38.1 C43.2 C44.2 J15.2 R24.1 R26.1 R32.1 R51.1 R63.1 R64.1 R65.1 U1.3(GND) U6.14(GND) U8.3(A)
uC3.3V: C1.1 C26.2 L4.2 R22.1 R68.1 U1.1(+VS) U6.19(DVDD)
VREF_PH: C39.2 C40.2 C41.2 J13.1 J15.1 J16.1 J17.1 J18.1 Q2.4(S) Q2.7(S) Q3.4(S) Q3.7(S) Q4.4(S) Q4.7(S) R53.1 R54.1 R55.1 R57.1 R58.1 R59.1 R71.2 U6.8(Vref)
3.3_REF: R67.1 ; port 3.3_REF
~{CS}: R27.2 ; port ~{CS}
B_G: R40.1 ; port B_G
B_IP: C41.1 J18.2 R50.1 R55.2 R59.2 R70.1 TP33.1 ; port B_IP
N_IP: C42.1 J19.2 R42.1 R56.2 R60.2 TP34.1 ; port N_IP
R: C33.1 R33.2 TP30.1 ; port R
R_G: R38.1 ; port R_G
R_IP: C39.1 J16.2 R44.1 R48.1 R53.2 R57.2 TP31.1 ; port R_IP
SCLK: R61.2 ; port SCLK
SDI: R23.2 ; port SDI
SDO: R62.2 ; port SDO
TEMP: C2.2 R1.2 ; port TEMP
VCC/2: C38.2 C42.2 J13.2 J14.2 J19.1 R52.2 R56.1 R60.1 R69.1 U8.2(C) ; port VCC/2
Y_G: R39.1 ; port Y_G
Y_IP: C40.1 J17.2 R43.1 R49.1 R54.2 R58.2 TP32.1 ; port Y_IP
NetC35_1: C35.1 R41.1 R42.2 U6.4(CH3)
NetC36_1: C36.1 R70.2 U6.5(CH2)
NetC43_1: C43.1 R44.2 U6.7(CH0)
NetC44_1: C44.1 R43.2 U6.6(CH1)
NetJ14_1: J14.1 R41.2
NetQ2_1: Q2.1(D) Q2.2(D) Q2.5(D) Q2.6(D) Q2.8(D) R48.2
NetQ2_3: Q2.3(G) R38.2
NetQ3_1: Q3.1(D) Q3.2(D) Q3.5(D) Q3.6(D) Q3.8(D) R49.2
NetQ3_3: Q3.3(G) R39.2
NetQ4_1: Q4.1(D) Q4.2(D) Q4.5(D) Q4.6(D) Q4.8(D) R50.2
NetQ4_3: Q4.3(G) R40.2
NetR1_1: R1.1 U1.2(VO)
NetR22_2: R22.2 U6.13(EN)
NetR23_1: R23.1 U6.17(DOUT)
NetR24_2: R24.2 TP39.1 U6.11(CH8)
NetR26_2: R26.2 TP37.1 U6.20(CH6)
NetR27_1: R27.1 U6.18(CS)
NetR32_2: R32.2 TP40.1 U6.10(CH7)
NetR33_1: R33.1 U6.9(VOUT)
NetR51_2: R51.2 R52.1 U8.1(FB)
NetR61_1: R61.1 U6.15(SCLK)
NetR62_1: R62.1 U6.16(DIN)
NetR63_2: R63.2 TP38.1 U6.12(CH9)
NetR64_2: R64.2 R71.1 TP35.1 U6.3(CH4)
NetR65_2: R65.2 TP36.1 U6.2(CH5)
NetR67_2: R67.2 R68.2 R69.2

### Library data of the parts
C1 C2 C26 C32 C38 = 06033C104JAT2A: as C16 on sheet Pg3
C33 C35 C36 C43 C44 = C1608C0G1E103J: as C17 on sheet Pg3
C39-C42 = 06033C101KAT2A: CAP, CERM, 100pF, 25V, +/-10%, X7R, 0603; Manufacturer: AVX; Polarized: N; CompType: Capacitor; U/M: EA; Cap_F: 0.0000000001; Tolerance_%: 10; Value1: Unknown; VDC_V: 25; TaMin_C: -55; TaMax_C: 125
J13-J15 = JUMPER_2X100MIL: Header, Male 2-pin, 100mil spacing,; Manufacturer: Sullins; PartNumber: PEC02SAAN; area: 20000; Value: PEC02SAAN
J16-J19 = ED120/2DS: as J12 on sheet Pg3
L4 = BLM18SG331TN1D: 1.5A Ferrite Bead, 330 ohm @ 100MHz, SMD; Manufacturer: MuRata; Imax_A: 1.5; DCR_ohm: 0.07; Value1: 0.07 ohm; ZTyp@100MHz_Ohm: 330; U/M: EA
Q2-Q4 = CSD17571Q2: as Q1 on sheet Pg3
R1 R33 R41 R68 = CRCW0603100RFKEA: RES, 100 ohm, 1%, 0.1W, 0603; Manufacturer: Vishay-Dale; CompType: Resistor; Value_Code: 100R; Tolerance_%: 1; Power_W: 0.1; VDC_V: 75; TempCo: 100 ppm/C; EIA_Code: E96; U/M: EA
R22 = CRCW060310K0FKEA: as R14 on sheet Pg3
R23 R27 R61 R62 = CRCW060310R0JNEA: RES, 10 ohm, 5%, 0.1W, 0603; Manufacturer: Vishay-Dale; CompType: Resistor; Value_Code: 10R0; Tolerance_%: 5; Power_W: 0.1; VDC_V: 75; TempCo: 200 ppm/C; EIA_Code: E24; U/M: EA
R24 R26 R32 R63-R65 R67 R71 = CRCW06030000Z0EA: RES, 0 ohm, 5%, 0.1W, 0603; Manufacturer: Vishay-Dale; CompType: Resistor; Value_Code: 0000; Tolerance_%: 5; Power_W: 0.1; VDC_V: 75; TempCo: 200 ppm/C; EIA_Code: E24; U/M: EA
R38-R40 = CRCW0603300RJNEA: as R4 on sheet Pg3
R42-R44 R70 = CRCW06031K00JNEA: RES, 1.0k ohm, 5%, 0.1W, 0603; Manufacturer: Vishay-Dale; CompType: Resistor; Res_ohm: 1000; Value_Code: 1k00; Tolerance_%: 5; Power_W: 0.1; VDC_V: 75; TempCo: 200 ppm/C; EIA_Code: E24; U/M: EA
R48-R50 R53-R60 = CSR1206FKR300: RES, 0.3 ohm, 1%, 0.5W, 1206; Manufacturer: Stackpole Electronics Inc; CompType: Resistor; Value_Code: R300; Tolerance_%: 1; Power_W: 0.5; TempCo: 100 ppm/C; EIA_Code: E96; U/M: EA
R51 = RNCF0603TKY10K0: as R36 on sheet Pg3
R52 = CRCW060330K0JNEA: RES, 30k ohm, 5%, 0.1W, 0603; Manufacturer: Vishay-Dale; CompType: Resistor; Res_ohm: 30000; Value_Code: 30k0; Tolerance_%: 5; Power_W: 0.1; VDC_V: 75; TempCo: 200 ppm/C; EIA_Code: E24; U/M: EA
R69 = CRCW0603470RJNEA: RES, 470 ohm, 5%, 0.1W, 0603; Manufacturer: Vishay-Dale; CompType: Resistor; Value_Code: 470R; Tolerance_%: 5; Power_W: 0.1; VDC_V: 75; TempCo: 200 ppm/C; EIA_Code: E24; U/M: EA
TP30-TP40 = TP-040_RND: as TP13 on sheet Pg3
U1 = LM62BIM3: 2.7V, 15.6mV/°C, Temperature Sensor, 3-pin SOT-23; Manufacturer: National Semiconductor; PackageTopMarking: T7B*XTT; PowerWise: N; CompType: Temp Sensor IC
U6 = PGA11xAIPW: ZerØ-Drift Programmable Gain Amplifier with MUX; Alternate Manufacturer: None; Manufacturer: Texas Instruments; SymbolCreator: x0120606; CompType: IC
U8 = LM4041BIDBZ: IC, Micropower Shunt Voltage Reference 100 ppm/°C, 45µA-12mA,  Adjustable; Manufacturer: TI; Alternate Manufacturer: None; Area: 25500

## Sheet Pg5.SchDoc
size 431 x 279 mm; Date: Not shown in title block; ApprovedBy: Not shown in title block; CheckedBy: Not shown in title block; Author: Not shown in title block; CompanyName: Not shown in title block; Engineer: Not shown in title block; Organization: Not shown in title block; Address1: Not shown in title block; Address2: Not shown in title block; Address3: Not shown in title block; Address4: Not shown in title block; DocumentNumber: 5; Revision: Use project parameter SCH_Rev; SheetNumber: 5; SheetTotal: 7; PageSetup: Record=PageOptions|CenterHorizontal=True|CenterVertical=True|PrintScale=0.59|XCorrection=1.00|YCorrection=1.00|PrintKind=0|BorderSize=5000000|LeftOffset=0|BottomOffset=0|Orientation=2|PaperLength=1000|PaperWidth=1000|Scale=100|PaperSource=15|PrintQuality=600|MediaType=1|DitherType=10|PaperKind=Letter|PrintScaleMode=1
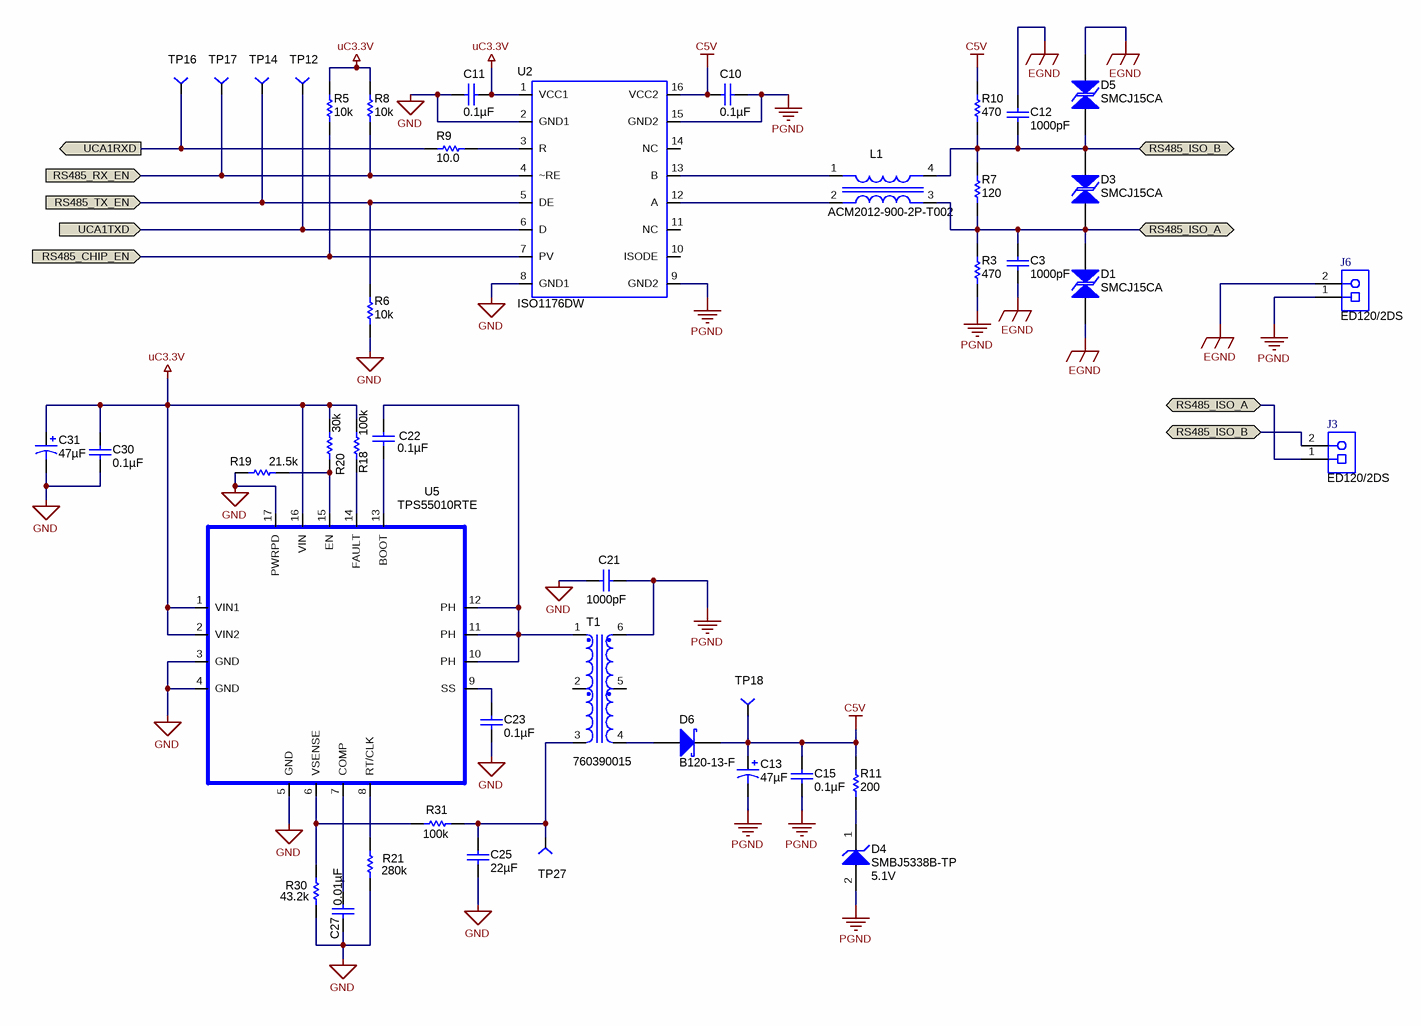
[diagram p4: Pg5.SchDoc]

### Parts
C3  ValueDisplayed: 1000pF  [1206]  (hidden comment: CC1206KKX7RCBB102)
C10  ValueDisplayed: 0.1µF  [0603]  (hidden comment: 06033C104JAT2A)
C11  ValueDisplayed: 0.1µF  [0603]  (hidden comment: 06033C104JAT2A)
C12  ValueDisplayed: 1000pF  [1206]  (hidden comment: CC1206KKX7RCBB102)
C13  ValueDisplayed: 47µF  [7343-43]  (hidden comment: T495X476K035ATE300)
C15  ValueDisplayed: 0.1µF  [0603]  (hidden comment: 06033C104JAT2A)
C21  ValueDisplayed: 1000pF  [1206]  (hidden comment: CC1206KKX7RCBB102)
C22  ValueDisplayed: 0.1µF  [0603]  (hidden comment: 06033C104JAT2A)
C23  ValueDisplayed: 0.1µF  [0603]  (hidden comment: 06033C104JAT2A)
C25  ValueDisplayed: 22µF  [1206]  (hidden comment: 1206YD226MAT2A)
C27  ValueDisplayed: 0.01µF  [0603]  (hidden comment: C1608C0G1E103J)
C30  ValueDisplayed: 0.1µF  [0603]  (hidden comment: 06033C104JAT2A)
C31  ValueDisplayed: 47µF  [7343-43]  (hidden comment: T495X476K035ATE300)
D1  SMCJ15CA  [SMC]
D3  SMCJ15CA  [SMC]
D4  SMBJ5338B-TP  value 5.1V  [SMB]
D5  SMCJ15CA  [SMC]
D6  B120-13-F  [SMA]
J3  ED120/2DS  [CONN_ED120-2DS]
J6  ED120/2DS  [CONN_ED120-2DS]
L1  ACM2012-900-2P-T002  [IND_0805-4P]
R3  value 470  [0805_HV]  (hidden comment: CRCW0805470RFKEA)
R5  value 10k  [0603]  (hidden comment: CRCW060310K0JNEA)
R6  value 10k  [0603]  (hidden comment: CRCW060310K0JNEA)
R7  value 120  [0805_HV]  (hidden comment: CRCW0805120RJNEA)
R8  value 10k  [0603]  (hidden comment: CRCW060310K0JNEA)
R9  value 10.0  [0603]  (hidden comment: CRCW060310R0FKEA)
R10  value 470  [0805_HV]  (hidden comment: CRCW0805470RFKEA)
R11  value 200  [0603]  (hidden comment: CRCW0603200RFKEA)
R18  value 100k  [0603]  (hidden comment: CRCW0603100KFKEA)
R19  value 21.5k  [0603]  (hidden comment: CRCW060321K5FKEA)
R20  value 30k  [0603]  (hidden comment: CRCW060330K0JNEA)
R21  value 280k  [0603]  (hidden comment: CRCW0603280KFKEA)
R30  value 43.2k  [0603]  (hidden comment: CRCW060343K2FKEA)
R31  value 100k  [0603]  (hidden comment: CRCW0603100KFKEA)
T1  760390015  [760390015]
TP12  TP-040_RND  [TP-040_RND]  (value not drawn)
TP14  TP-040_RND  [TP-040_RND]  (value not drawn)
TP16  TP-040_RND  [TP-040_RND]  (value not drawn)
TP17  TP-040_RND  [TP-040_RND]  (value not drawn)
TP18  TP-040_RND  [TP-040_RND]  (value not drawn)
TP27  TP-040_RND  [TP-040_RND]  (value not drawn)
U2  ISO1176DW  [DW0016A_N]
U5  TPS55010RTE  [RTE-16]

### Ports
RS485_CHIP_EN (in), RS485_ISO_A (bidir), RS485_ISO_B (bidir), RS485_RX_EN (in), RS485_TX_EN (in), UCA1RXD (out), UCA1TXD (in)

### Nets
C5V: C10.2 C13.1(+) C15.1 D6.1(K) R10.2 R11.2 TP18.1 U2.16(VCC2)
EGND: C3.2 C12.1 D1.1 D5.2 J6.2
GND: C11.1 C21.2 C23.1 C25.2 C27.2 C30.2 C31.2(-) R6.1 R19.1 R21.1 R30.1 U2.2(GND1) U2.8(GND1) U5.3(GND) U5.4(GND) U5.5(GND) U5.17(PWRPD)
PGND: C10.1 C13.2(-) C15.2 C21.1 D4.2(A) J6.1 R3.1 T1.6 U2.9(GND2) U2.15(GND2)
uC3.3V: C11.2 C30.1 C31.1(+) R5.2 R8.2 R18.2 R20.2 U2.1(VCC1) U5.1(VIN1) U5.2(VIN2) U5.16(VIN)
RS485_CHIP_EN: R5.1 U2.7(PV) ; port RS485_CHIP_EN
RS485_ISO_A: C3.1 D1.2 D3.1 J3.1 L1.3 R3.2 R7.1 ; port RS485_ISO_A
RS485_ISO_B: C12.2 D3.2 D5.1 J3.2 L1.4 R7.2 R10.1 ; port RS485_ISO_B
RS485_RX_EN: R8.1 TP17.1 U2.4(~RE) ; port RS485_RX_EN
RS485_TX_EN: R6.2 TP14.1 U2.5(DE) ; port RS485_TX_EN
UCA1RXD: R9.1 TP16.1 ; port UCA1RXD
UCA1TXD: TP12.1 U2.6(D) ; port UCA1TXD
NetC22_1: C22.1 T1.1 U5.10(PH) U5.11(PH) U5.12(PH)
NetC22_2: C22.2 U5.13(BOOT)
NetC23_2: C23.2 U5.9(SS)
NetC25_1: C25.1 R31.1 T1.3 TP27.1
NetC27_1: C27.1 U5.7(COMP)
NetD4_1: D4.1(K) R11.1
NetD6_2: D6.2(A) T1.4
NetL1_1: L1.1 U2.13(B)
NetL1_2: L1.2 U2.12(A)
NetR9_2: R9.2 U2.3(R)
NetR18_1: R18.1 U5.14(FAULT)
NetR19_2: R19.2 R20.1 U5.15(EN)
NetR21_2: R21.2 U5.8(RT/CLK)
NetR30_2: R30.2 R31.2 U5.6(VSENSE)

Not connected (* = marked no-connect by the designer): T1 2 5; U2 10(ISODE) 11(NC) 14(NC)

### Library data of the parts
C3 C12 C21 = CC1206KKX7RCBB102: CAP, CERM, 1000pF, 1000V, +/-10%, X7R, 1206; Manufacturer: Yageo America; Polarized: N; CompType: Capacitor; U/M: EA; Cap_F: 0.000000001; Tolerance_%: 10; Value1: Unknown; VDC_V: 1000; TaMin_C: -55; TaMax_C: 125
C10 C11 C15 C22 C23 C30 = 06033C104JAT2A: as C16 on sheet Pg3
C13 C31 = T495X476K035ATE300: CAP, TA, 47uF, 35V, +/-10%, 0.3 ohm, SMD; Manufacturer: Kemet; Polarized: Y; CompType: Capacitor; U/M: EA; Cap_F: 0.000047; Tolerance_%: 10; Value1: 0.3 ohm; VDC_V: 35; ESR_Ohm: 0.3; IRMS_A: 0.667; TaMin_C: -55; TaMax_C: 125; Cap_Case: X
C25 = 1206YD226MAT2A: CAP, CERM, 22uF, 16V, +/-20%, X5R, 1206; Manufacturer: AVX; Polarized: N; CompType: Capacitor; U/M: EA; Cap_F: 0.000022; Tolerance_%: 20; Value1: Unknown; VDC_V: 16; TaMin_C: -55; TaMax_C: 85
C27 = C1608C0G1E103J: as C17 on sheet Pg3
D1 D3 D5 = SMCJ15CA: Diode, TVS 15V 1500W BIDIR 5% SMC; Manufacturer: Littelfuse Inc; Power_W: 1500
D4 = SMBJ5338B-TP: Diode, Zener, 5.1V, 5W, SMB; Manufacturer: Micro Commercial Components; U/M: EA; Power_W: 5; Vz_V: 5.1; RJA_CperW: 25
D6 = B120-13-F: Diode, Schottky, 20V, 1A, SMA; Manufacturer: Diodes Inc.; U/M: EA; Vf_V: 0.5; Value2: 0.5V; Io_A: 1; Vr_V: 20; TJmax_C: 150
J3 J6 = ED120/2DS: as J12 on sheet Pg3
L1 = IND_ACM2012_SERIES: Inductor, Common Mode Filter SMD; Manufacturer: TDK; Area: 8.13 mm; Value: xx uH
R3 R10 = CRCW0805470RFKEA: RES, 470 ohm, 1%, 0.125W, 0805; Manufacturer: Vishay-Dale; CompType: Resistor; Value_Code: 470R; Tolerance_%: 1; Power_W: 0.125; VDC_V: 150; TempCo: 100 ppm/C; U/M: EA
R5 R6 R8 = CRCW060310K0JNEA: RES, 10k ohm, 5%, 0.1W, 0603; Manufacturer: Vishay-Dale; CompType: Resistor; Res_ohm: 10000; Value_Code: 10k0; Tolerance_%: 5; Power_W: 0.1; VDC_V: 75; TempCo: 200 ppm/C; EIA_Code: E24; U/M: EA
R7 = CRCW0805120RJNEA: RES, 120 ohm, 5%, 0.125W, 0805; Manufacturer: Vishay-Dale; CompType: Resistor; Value_Code: 120R; Tolerance_%: 5; Power_W: 0.125; VDC_V: 150; TempCo: 200 ppm/C; EIA_Code: E24; U/M: EA
R9 = CRCW060310R0FKEA: RES, 10.0 ohm, 1%, 0.1W, 0603; Manufacturer: Vishay-Dale; CompType: Resistor; Res_ohm: 10; Value_Code: 10R0; Tolerance_%: 1; Power_W: 0.1; VDC_V: 75; TempCo: 100 ppm/C; EIA_Code: E96; U/M: EA
R11 = CRCW0603200RFKEA: RES, 200 ohm, 1%, 0.1W, 0603; Manufacturer: Vishay-Dale; CompType: Resistor; Value_Code: 200R; Tolerance_%: 1; Power_W: 0.1; VDC_V: 75; TempCo: 100 ppm/C; EIA_Code: E96; U/M: EA
R18 R31 = CRCW0603100KFKEA: RES, 100k ohm, 1%, 0.1W, 0603; Manufacturer: Vishay-Dale; CompType: Resistor; Res_ohm: 100000; Tolerance_%: 1; Power_W: 0.1; VDC_V: 75; TempCo: 100 ppm/C; EIA_Code: E96; U/M: EA
R19 = CRCW060321K5FKEA: RES, 21.5k ohm, 1%, 0.1W, 0603; Manufacturer: Vishay-Dale; CompType: Resistor; Res_ohm: 21500; Value_Code: 21k5; Tolerance_%: 1; Power_W: 0.1; VDC_V: 75; TempCo: 100 ppm/C; EIA_Code: E96; U/M: EA
R20 = CRCW060330K0JNEA: as R52 on sheet Pg4
R21 = CRCW0603280KFKEA: RES, 280k ohm, 1%, 0.1W, 0603; Manufacturer: Vishay-Dale; CompType: Resistor; Res_ohm: 280000; Tolerance_%: 1; Power_W: 0.1; VDC_V: 75; TempCo: 100 ppm/C; EIA_Code: E96; U/M: EA
R30 = CRCW060343K2FKEA: RES, 43.2k ohm, 1%, 0.1W, 0603; Manufacturer: Vishay-Dale; CompType: Resistor; Res_ohm: 43200; Value_Code: 43k2; Tolerance_%: 1; Power_W: 0.1; VDC_V: 75; TempCo: 100 ppm/C; EIA_Code: E96; U/M: EA
T1 = TRNSFMR 760390015: Transformer 475uH SMD; Manufacturer: Wurth Electronics Midcom
TP12 TP14 TP16-TP18 TP27 = TP-040_RND: as TP13 on sheet Pg3
U2 = ISO1176DW: IC, ISOLATED RS-485 PROFIBUS TRANSCEIVER; Manufacturer: TI; Alternate Manufacturer: None; Area: 215160
U5 = TPS55010RTE: IC, DC-DC Converter; Manufacturer: TI; Alternate Manufacturer: None; Area: 33856

## Sheet Pg6.SchDoc
size A4; Date: Not shown in title block; ApprovedBy: Not shown in title block; CheckedBy: Not shown in title block; Author: Not shown in title block; CompanyName: Not shown in title block; Engineer: Not shown in title block; Organization: Not shown in title block; Address1: Not shown in title block; Address2: Not shown in title block; Address3: Not shown in title block; Address4: Not shown in title block; DocumentNumber: 6; Revision: Use project parameter SCH_Rev; SheetNumber: 6; SheetTotal: 7; PageSetup: Record=PageOptions|CenterHorizontal=True|CenterVertical=True|PrintScale=1.00|XCorrection=1.00|YCorrection=1.00|PrintKind=0|BorderSize=5000000|LeftOffset=0|BottomOffset=0|Orientation=2|PaperLength=1000|PaperWidth=1000|Scale=100|PaperSource=15|PrintQuality=600|MediaType=1|DitherType=10|PaperKind=Letter|PrintScaleMode=1
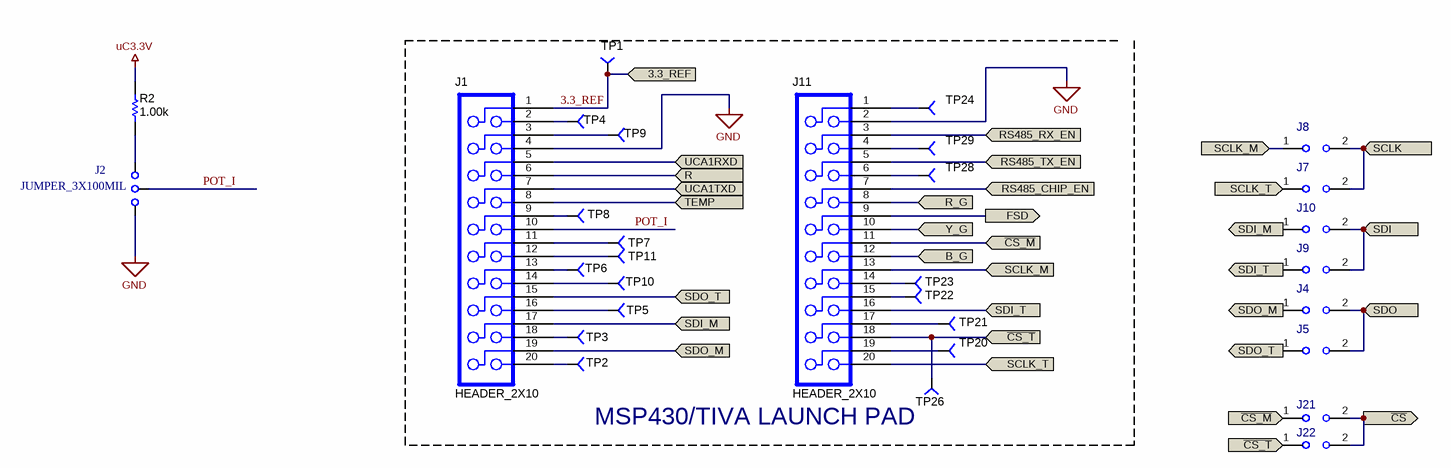
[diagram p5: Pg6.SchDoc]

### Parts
J1  HEADER_2X10  [HEADER_2X10P]
J2  JUMPER_3X100MIL  [HDR100_1X3]
J4  JUMPER_2X100MIL  [HDR100_1X2]  (value not drawn)
J5  JUMPER_2X100MIL  [HDR100_1X2]  (value not drawn)
J7  JUMPER_2X100MIL  [HDR100_1X2]  (value not drawn)
J8  JUMPER_2X100MIL  [HDR100_1X2]  (value not drawn)
J9  JUMPER_2X100MIL  [HDR100_1X2]  (value not drawn)
J10  JUMPER_2X100MIL  [HDR100_1X2]  (value not drawn)
J11  HEADER_2X10  [HEADER_2X10P]
J21  JUMPER_2X100MIL  [HDR100_1X2]  (value not drawn)
J22  JUMPER_2X100MIL  [HDR100_1X2]  (value not drawn)
R2  value 1.00k  [0805_HV]  (hidden comment: CRCW08051K00FKEA)
TP1  TP-040_RND  [TP-040_RND]  (value not drawn)
TP2  TP-040_RND  [TP-040_RND]  (value not drawn)
TP3  TP-040_RND  [TP-040_RND]  (value not drawn)
TP4  TP-040_RND  [TP-040_RND]  (value not drawn)
TP5  TP-040_RND  [TP-040_RND]  (value not drawn)
TP6  TP-040_RND  [TP-040_RND]  (value not drawn)
TP7  TP-040_RND  [TP-040_RND]  (value not drawn)
TP8  TP-040_RND  [TP-040_RND]  (value not drawn)
TP9  TP-040_RND  [TP-040_RND]  (value not drawn)
TP10  TP-040_RND  [TP-040_RND]  (value not drawn)
TP11  TP-040_RND  [TP-040_RND]  (value not drawn)
TP20  TP-040_RND  [TP-040_RND]  (value not drawn)
TP21  TP-040_RND  [TP-040_RND]  (value not drawn)
TP22  TP-040_RND  [TP-040_RND]  (value not drawn)
TP23  TP-040_RND  [TP-040_RND]  (value not drawn)
TP24  TP-040_RND  [TP-040_RND]  (value not drawn)
TP26  TP-040_RND  [TP-040_RND]  (value not drawn)
TP28  TP-040_RND  [TP-040_RND]  (value not drawn)
TP29  TP-040_RND  [TP-040_RND]  (value not drawn)

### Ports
3.3_REF (in), B_G (in), FSD (out), R, R_G (in), RS485_CHIP_EN (in), RS485_RX_EN (in), RS485_TX_EN (in), SCLK (in), SCLK_M (in), SCLK_T (in), SDI, SDI_M, SDI_T, SDO, SDO_M, SDO_T, TEMP, UCA1RXD, UCA1TXD, Y_G (in), ~{CS_M} (in), ~{CS_T} (in), ~{CS} (in)

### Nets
GND: J1.4 J2.3 J11.2
uC3.3V: R2.2
3.3_REF: J1.1 TP1.1 ; port 3.3_REF
~{CS}: J21.2 J22.2 ; port ~{CS}
~{CS_M}: J11.11 J21.1 ; port ~{CS_M}
~{CS_T}: J11.18 J22.1 TP26.1 ; port ~{CS_T}
B_G: J11.12 ; port B_G
FSD: J11.9 ; port FSD
POT_I: J1.10 J2.2
R: J1.6 ; port R
R_G: J11.8 ; port R_G
RS485_CHIP_EN: J11.7 ; port RS485_CHIP_EN
RS485_RX_EN: J11.3 ; port RS485_RX_EN
RS485_TX_EN: J11.5 ; port RS485_TX_EN
SCLK: J7.2 J8.2 ; port SCLK
SCLK_M: J8.1 J11.13 ; port SCLK_M
SCLK_T: J7.1 J11.20 ; port SCLK_T
SDI: J9.2 J10.2 ; port SDI
SDI_M: J1.17 J10.1 ; port SDI_M
SDI_T: J9.1 J11.16 ; port SDI_T
SDO: J4.2 J5.2 ; port SDO
SDO_M: J1.19 J4.1 ; port SDO_M
SDO_T: J1.15 J5.1 ; port SDO_T
TEMP: J1.8 ; port TEMP
UCA1RXD: J1.5 ; port UCA1RXD
UCA1TXD: J1.7 ; port UCA1TXD
Y_G: J11.10 ; port Y_G
NetJ1_2: J1.2 TP4.1
NetJ1_3: J1.3 TP9.1
NetJ1_9: J1.9 TP8.1
NetJ1_11: J1.11 TP7.1
NetJ1_12: J1.12 TP11.1
NetJ1_13: J1.13 TP6.1
NetJ1_14: J1.14 TP10.1
NetJ1_16: J1.16 TP5.1
NetJ1_18: J1.18 TP3.1
NetJ1_20: J1.20 TP2.1
NetJ2_1: J2.1 R2.1
NetJ11_1: J11.1 TP24.1
NetJ11_4: J11.4 TP29.1
NetJ11_6: J11.6 TP28.1
NetJ11_14: J11.14 TP23.1
NetJ11_15: J11.15 TP22.1
NetJ11_17: J11.17 TP21.1
NetJ11_19: J11.19 TP20.1

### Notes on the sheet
- MSP430/TIVA LAUNCH PAD

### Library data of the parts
J1 J11 = HEADER_2X10: Header, Male 2x10-pin, 100mil spacing; PartNumber: PEC10DAAN; Manufacturer: Sullins; Area: 200000; Value: PEC10DAAN
J2 = JUMPER_3X100MIL: Header, Male 3-pin, 100mil spacing,; Manufacturer: Sullins; PartNumber: PEC03SAAN; area: 30000; Value: PEC03SAAN
J4 J5 J7-J10 J21 J22 = JUMPER_2X100MIL: as J13 on sheet Pg4
R2 = CRCW08051K00FKEA: RES, 1.00k ohm, 1%, 0.125W, 0805; Manufacturer: Vishay-Dale; CompType: Resistor; Res_ohm: 1000; Value_Code: 1k00; Tolerance_%: 1; Power_W: 0.125; VDC_V: 150; TempCo: 100 ppm/C; EIA_Code: E96; U/M: EA
TP1-TP11 TP20-TP24 TP26 TP28 TP29 = TP-040_RND: as TP13 on sheet Pg3

## Sheet Pg7 Hardware.SchDoc
size 431 x 279 mm; Date: Not shown in title block; ApprovedBy: Not shown in title block; CheckedBy: Not shown in title block; Author: Not shown in title block; CompanyName: Not shown in title block; Engineer: Not shown in title block; Organization: Not shown in title block; Address1: Not shown in title block; Address2: Not shown in title block; Address3: Not shown in title block; Address4: Not shown in title block; DocumentNumber: 7; Revision: Use project parameter SCH_Rev; SheetNumber: 7; SheetTotal: 7; PageSetup: Record=PageOptions|CenterHorizontal=True|CenterVertical=True|PrintScale=1.00|XCorrection=1.00|YCorrection=1.00|PrintKind=0|BorderSize=5000000|LeftOffset=0|BottomOffset=0|Orientation=2|PaperLength=1000|PaperWidth=1000|Scale=100|PaperSource=15|PrintQuality=600|MediaType=1|DitherType=10|PaperKind=Letter|PrintScaleMode=1
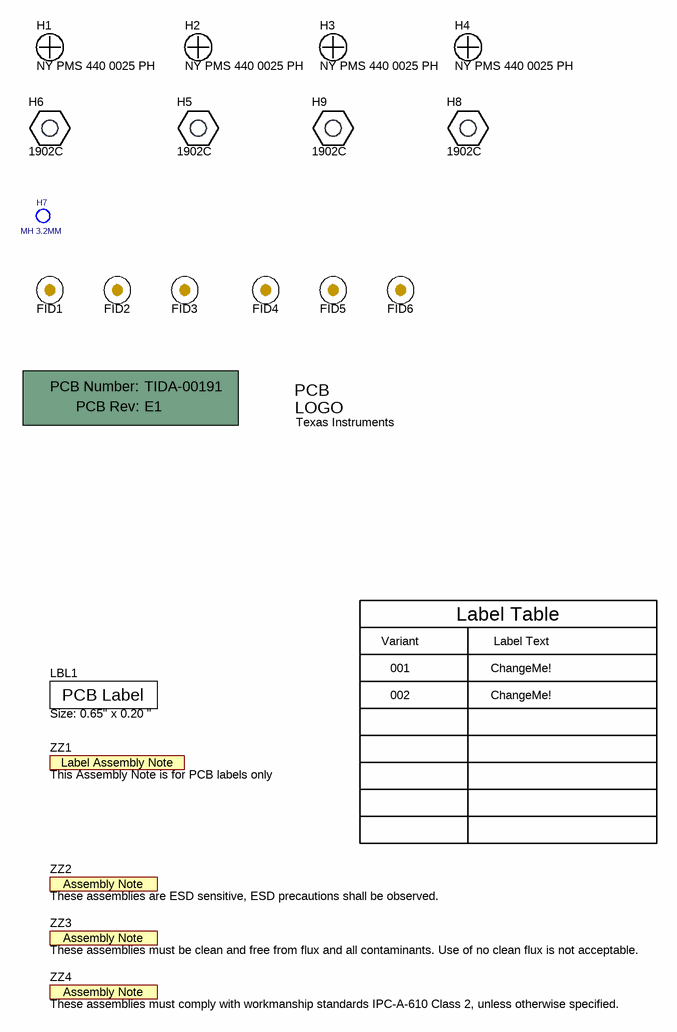
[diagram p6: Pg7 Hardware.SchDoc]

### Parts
!PCB1  Printed Circuit Board  (value not drawn)  (mechanical)
FID1  Fiducial  [Fiducial10-20]  (value not drawn)
FID2  Fiducial  [Fiducial10-20]  (value not drawn)
FID3  Fiducial  [Fiducial10-20]  (value not drawn)
FID4  Fiducial  [Fiducial10-20]  (value not drawn)
FID5  Fiducial  [Fiducial10-20]  (value not drawn)
FID6  Fiducial  [Fiducial10-20]  (value not drawn)
H1  NY PMS 440 0025 PH  [NY PMS 440 0025 PH]
H2  NY PMS 440 0025 PH  [NY PMS 440 0025 PH]
H3  NY PMS 440 0025 PH  [NY PMS 440 0025 PH]
H4  NY PMS 440 0025 PH  [NY PMS 440 0025 PH]
H5  1902C  [Keystone_1902C]
H6  1902C  [Keystone_1902C]
H7  MH 3.2MM  [MH3.2_H5_W6_KO8_STARHEAD]
H8  1902C  [Keystone_1902C]
H9  1902C  [Keystone_1902C]
LBL1  Size: 0.65" x 0.20 "  [Label_650x200]
Logo1  Texas Instruments  [TI_Stacked_SolderMask_Small]  (no BOM)
ZZ1  This Assembly Note is for PCB labels only  [AssemblyNoteLabel]  (no BOM)
ZZ2  These assemblies are ESD sensitive, ESD precautions shall be observed.  [AssemblyNote]  (no BOM)
ZZ3  These assemblies must be clean and free from flux and all contaminants. Use of no clean flux is not acceptable.  [AssemblyNote]  (no BOM)
ZZ4  These assemblies must comply with workmanship standards IPC-A-610 Class 2, unless otherwise specified.  [AssemblyNote]  (no BOM)

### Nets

Not connected (* = marked no-connect by the designer): H7 1

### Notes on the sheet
- Variant
- Label Table
- Label Text
- 001
- 002
- ChangeMe!

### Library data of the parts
!PCB1 = PCB: Manufacturer: Any; PartNumber: TIDA-00191; SymbolCreator: a0412235
FID1-FID6 = Fiducial: Fiducial mark.  There is nothing to buy or mount.; SymbolCreator: codlsc
H1-H4 = NY PMS 440 0025 PH: Machine Screw, Round, #4-40 x 1/4, Nylon, Philips panhead; Manufacturer: B&F Fastener Supply; CompType: Hardware; SymbolCreator: codlsc; U/M: EA
H5 H6 H8 H9 = 1902C: Standoff, Hex, 0.5"L #4-40 Nylon; Manufacturer: Keystone; CompType: Hardware
H7 = MH 3_0.5MM: Mountin hole, NPTH Drill 3.2mm
LBL1 = THT-14-423-10: Thermal Transfer Printable Labels, 0.650" W x 0.200" H - 10,000 per roll; Manufacturer: Brady; SymbolCreator: a0412235; CompType: Label
Logo1 = TI_Logo: Texas Instrument Corporate Signature; SymbolCreator: codlsc
ZZ1 = AssemblyNoteLabel: SymbolCreator: a0412235
ZZ2-ZZ4 = AssemblyNote: SymbolCreator: codlsc

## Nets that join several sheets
GND: Pg3 (29 pins), Pg4 (21 pins), Pg5 (17 pins), Pg6 (J1.4 J2.3 J11.2)
uC3.3V: Pg3 (5 pins), Pg4 (7 pins), Pg5 (11 pins), Pg6 (R2.2)
3.3_REF: Pg4 (R67.1), Pg6 (J1.1 TP1.1)
~{CS}: Pg4 (R27.2), Pg6 (J21.2 J22.2)
B_G: Pg4 (R40.1), Pg6 (J11.12)
FSD: Pg3 (R37.1), Pg6 (J11.9)
R: Pg4 (C33.1 R33.2 TP30.1), Pg6 (J1.6)
R_G: Pg4 (R38.1), Pg6 (J11.8)
RS485_CHIP_EN: Pg5 (R5.1 U2.7), Pg6 (J11.7)
RS485_RX_EN: Pg5 (R8.1 TP17.1 U2.4), Pg6 (J11.3)
RS485_TX_EN: Pg5 (R6.2 TP14.1 U2.5), Pg6 (J11.5)
SCLK: Pg4 (R61.2), Pg6 (J7.2 J8.2)
SDI: Pg4 (R23.2), Pg6 (J9.2 J10.2)
SDO: Pg4 (R62.2), Pg6 (J4.2 J5.2)
TEMP: Pg4 (C2.2 R1.2), Pg6 (J1.8)
UCA1RXD: Pg5 (R9.1 TP16.1), Pg6 (J1.5)
UCA1TXD: Pg5 (TP12.1 U2.6), Pg6 (J1.7)
Y_G: Pg4 (R39.1), Pg6 (J11.10)

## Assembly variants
001: not fitted C37 D7 D10 D12 J2 Q2 Q3 Q4 Q5 R2 R28 R34 R35 R36 R38 R39 R40 R45 R46 R47 R48 R49 R50 R66 R67 R71 U7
